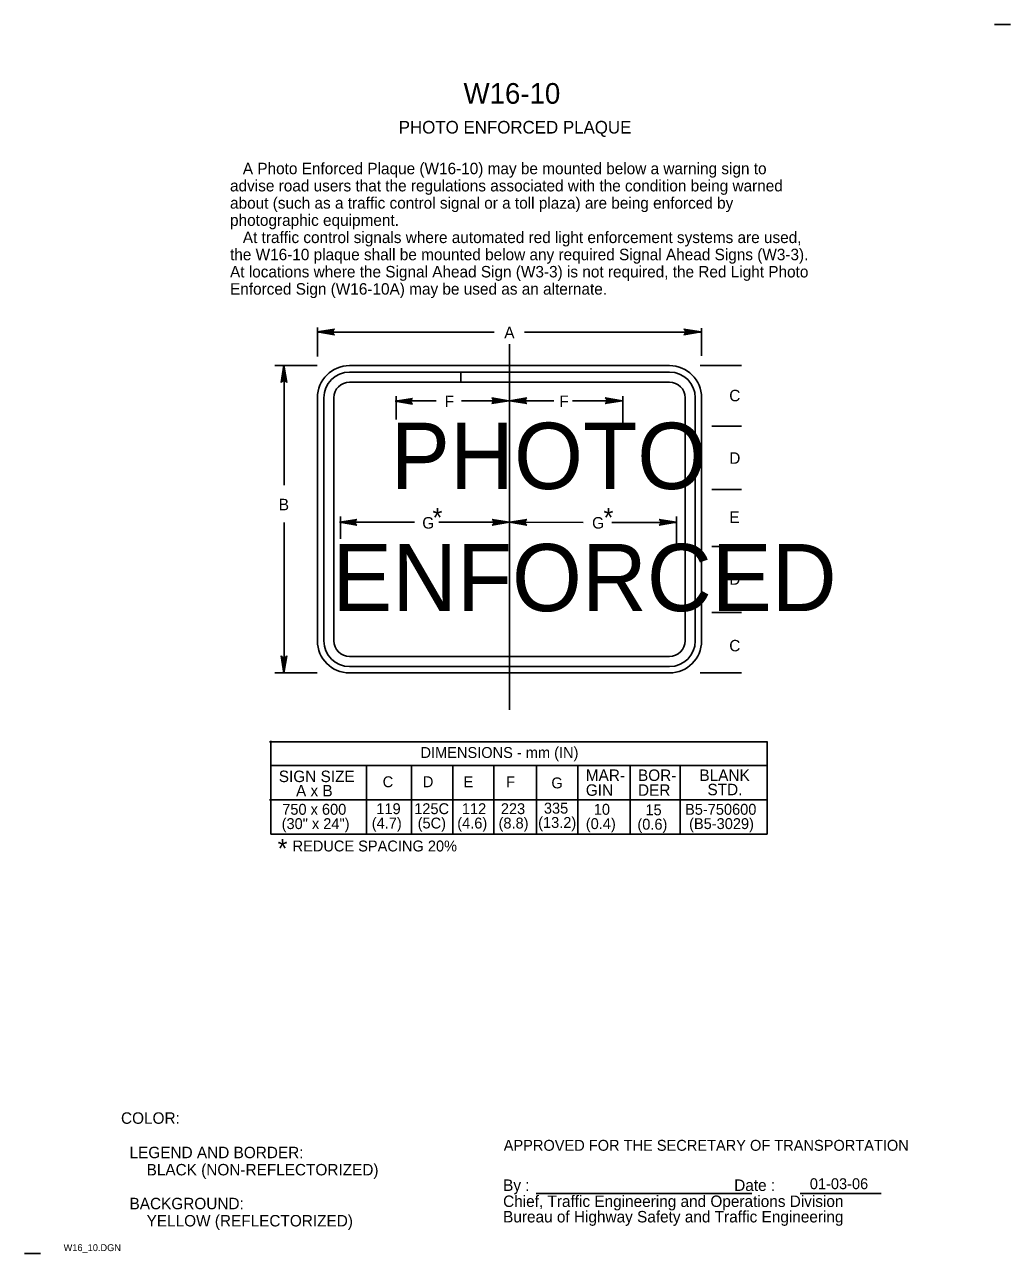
# Model space of a CAD drawing. Extents: x 0.004 to 0.219, y 0.004 to 0.272.
import ezdxf

# ---------------------------------------------------------------- set-up
doc = ezdxf.new("R2010")
doc.units = 0
for name, color, linetype in [('1', 7, 'Continuous'), ('2', 7, 'Continuous'), ('3', 7, 'Continuous'), ('4', 7, 'Continuous'), ('63', 7, 'Continuous')]:
    doc.layers.add(name, color=color, linetype=linetype)

# ---------------------------------------------------------------- blocks, each defined once
blk = doc.blocks.new('RARROW')
at = {"layer": '3'}
for p, q in [((-2.156, 0.285), (-2.2665, 0.384625)), ((-2.2665, 0.384625), (0, 0)), ((0, 0), (-2.2665, -0.379125)), ((-2.156, 0.285), (-2.075625, 0.12075)), ((0, 0), (-2.156, 0.285)), ((-2.14975, -0.2705), (0, 0)), ((-2.075625, 0.12075), (0, 0)), ((0, 0), (-2.074, -0.108)), ((-2.2665, -0.379125), (-2.14975, -0.2705)), ((-2.074, -0.108), (-2.14975, -0.2705))]:
    blk.add_line(p, q, dxfattribs=at)

msp = doc.modelspace()

# ---------------------------------------------------------------- linework, layer by layer
at = {"layer": '1'}
for p, q in [((0.10976, 0.20209), (0.10976, 0.12238)), ((0.05865, 0.19741), (0.06789, 0.19741)), ((0.06067, 0.17136), (0.06067, 0.19741)), ((0.14461, 0.19741), (0.07491, 0.19741)), ((0.09918, 0.19601), (0.07491, 0.19601)), ((0.09918, 0.19381), (0.09918, 0.19601)), ((0.09918, 0.19381), (0.09918, 0.19601)), ((0.14461, 0.19601), (0.09918, 0.19601)), ((0.09918, 0.19601), (0.09918, 0.19381)), ((0.07491, 0.19381), (0.09918, 0.19381)), ((0.09918, 0.19381), (0.14461, 0.19381)), ((0.06791, 0.13741), (0.06791, 0.19041)), ((0.06931, 0.19041), (0.06931, 0.13741)), ((0.07151, 0.13741), (0.07151, 0.19041)), ((0.08506, 0.19077), (0.08506, 0.18569)), ((0.13446, 0.19077), (0.13446, 0.18436)), ((0.14801, 0.19041), (0.14801, 0.13741)), ((0.15021, 0.13741), (0.15021, 0.19041)), ((0.15161, 0.13741), (0.15161, 0.19041)), ((0.16032, 0.18419), (0.15382, 0.18419)), ((0.15161, 0.13741), (0.15161, 0.17341)), ((0.16032, 0.17039), (0.15382, 0.17039)), ((0.07291, 0.15967), (0.07291, 0.16451)), ((0.14615, 0.15816), (0.14615, 0.16451)), ((0.06067, 0.13041), (0.06067, 0.16318)), ((0.16032, 0.15799), (0.15382, 0.15799)), ((0.16032, 0.14362), (0.15382, 0.14362)), ((0.14461, 0.13401), (0.07491, 0.13401)), ((0.07491, 0.13181), (0.14461, 0.13181)), ((0.05865, 0.13041), (0.06789, 0.13041)), ((0.14461, 0.13041), (0.07491, 0.13041)), ((0.16032, 0.13041), (0.15126, 0.13041)), ((0.11556, 0.01695), (0.16257, 0.01695)), ((0.17308, 0.01695), (0.19069, 0.01695))]:
    msp.add_line(p, q, dxfattribs=at)
for centre, radius, start, end in [((0.07491, 0.19041), 0.007, 90, 180), ((0.07491, 0.19041), 0.0056, 90, 180), ((0.14461, 0.19041), 0.007, 0, 90), ((0.14461, 0.19041), 0.0056, 0, 90), ((0.07491, 0.19041), 0.0034, 90, 180), ((0.14461, 0.19041), 0.0034, 0, 90), ((0.07491, 0.13741), 0.007, 180, 270), ((0.07491, 0.13741), 0.0056, 180, 270), ((0.07491, 0.13741), 0.0034, 180, 270), ((0.14461, 0.13741), 0.007, 270, 0), ((0.14461, 0.13741), 0.0056, 270, 0), ((0.14461, 0.13741), 0.0034, 270, 0)]:
    msp.add_arc(centre, radius, start, end, dxfattribs=at)
at = {"layer": '3'}
for p, q in [((0.06791, 0.19943), (0.06791, 0.20571)), ((0.10643, 0.2047), (0.06791, 0.2047)), ((0.1516, 0.2047), (0.11299, 0.2047)), ((0.1516, 0.19954), (0.1516, 0.20556)), ((0.15126, 0.19741), (0.16031, 0.19742)), ((0.09377, 0.18974), (0.08506, 0.18974)), ((0.10976, 0.18974), (0.09929, 0.18974)), ((0.11943, 0.18974), (0.10976, 0.18974)), ((0.13446, 0.18974), (0.12346, 0.18974)), ((0.08906, 0.16328), (0.07291, 0.1633)), ((0.10976, 0.16326), (0.09438, 0.16327)), ((0.12584, 0.16324), (0.10976, 0.16326)), ((0.14615, 0.16322), (0.13207, 0.16323)), ((0.0575, 0.11538), (0.16587, 0.11538)), ((0.05774, 0.11563), (0.05774, 0.09525)), ((0.16588, 0.11544), (0.16588, 0.09525)), ((0.16588, 0.11025), (0.05774, 0.11025)), ((0.07858, 0.11025), (0.07858, 0.09525)), ((0.13602, 0.11025), (0.13602, 0.09525)), ((0.14695, 0.11025), (0.14695, 0.09525)), ((0.0575, 0.10275), (0.16587, 0.10275)), ((0.16588, 0.09525), (0.05774, 0.09525))]:
    msp.add_line(p, q, dxfattribs=at)
for points in [[(0.08839, 0.11025), (0.08839, 0.09525)], [(0.09744, 0.11025), (0.09744, 0.09525)], [(0.10636, 0.11025), (0.10636, 0.09525)], [(0.11561, 0.11025), (0.11561, 0.09525)], [(0.12464, 0.11025), (0.12464, 0.09525)]]:
    msp.add_lwpolyline(points, dxfattribs=at)
at = {"layer": '63'}
for p, q in [((0.21888, 0.27175), (0.21538, 0.27175)), ((0.00762, 0.00387), (0.00413, 0.00387))]:
    msp.add_line(p, q, dxfattribs=at)

# ---------------------------------------------------------------- block references
at = {"layer": '3'}
for p, xscale, yscale, rotation in [((0.06788, 0.20475), 0.0016545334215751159, 0.0016366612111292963, 179.91708286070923), ((0.1515, 0.20475), 0.0016545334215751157, 0.001636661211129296, -0.08291713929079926), ((0.06062, 0.1975), 0.0016545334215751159, 0.0016366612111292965, 90.08291713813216), ((0.08488, 0.18963), 0.0016545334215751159, 0.0016366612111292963, 179.91708286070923), ((0.10963, 0.18975), 0.0016545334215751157, 0.001636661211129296, -0.08291713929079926), ((0.10975, 0.18975), 0.0016545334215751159, 0.0016366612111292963, 179.91708286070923), ((0.13437, 0.18975), 0.0016545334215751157, 0.001636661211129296, -0.08291713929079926), ((0.07275, 0.16325), 0.001654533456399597, 0.0016530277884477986, 179.91625369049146), ((0.10975, 0.16325), 0.0016545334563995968, 0.0016530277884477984, -0.08374630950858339), ((0.10975, 0.16325), 0.001654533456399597, 0.0016530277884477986, 179.91625369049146), ((0.14613, 0.16325), 0.0016545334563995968, 0.0016530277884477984, -0.08374630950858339), ((0.06062, 0.13037), 0.0016545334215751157, 0.0016366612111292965, -89.91708286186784)]:
    msp.add_blockref('RARROW', p, dxfattribs=dict(at, xscale=xscale, yscale=yscale, rotation=rotation))

# ---------------------------------------------------------------- texts
at = {"layer": '1'}
for s, height, p in [('W16-10', 0.0045, (0.09975, 0.2545)), ('PHOTO ENFORCED PLAQUE', 0.0027503, (0.08563, 0.248)), ('PHOTO', 0.014459, (0.08388, 0.1705)), ('*', 0.0041, (0.093, 0.16225)), ('*', 0.0041, (0.13025, 0.16225)), ('ENFORCED', 0.014645, (0.07113, 0.14388)), ('*', 0.0041, (0.05925, 0.09012)), ('COLOR:', 0.0025, (0.02513, 0.03213)), ('  LEGEND AND BORDER:', 0.0024998, (0.02513, 0.02463)), ('APPROVED FOR THE SECRETARY OF TRANSPORTATION', 0.0023752, (0.1085, 0.02625)), ('      BLACK (NON-REFLECTORIZED)', 0.0024998, (0.02513, 0.02088)), ('By :                                                Date :', 0.0024998, (0.10837, 0.0175)), ('Chief, Traffic Engineering and Operations Division', 0.0024998, (0.10837, 0.014)), ('  BACKGROUND:', 0.0024998, (0.02513, 0.0135)), ('      YELLOW (REFLECTORIZED)', 0.0024998, (0.02513, 0.00975)), ('Bureau of Highway Safety and Traffic Engineering', 0.0024998, (0.10837, 0.01063)), ('W16_10.DGN', 0.0015, (0.01263, 0.00438))]:
    msp.add_text(s, height=height, dxfattribs=at).set_placement(p)
at = {"layer": '2'}
for s, p in [('   A Photo Enforced Plaque (W16-10) may be mounted below a warning sign to', (0.04888, 0.23913)), ('advise road users that the regulations associated with the condition being warned', (0.04888, 0.23538)), ('about (such as a traffic control signal or a toll plaza) are being enforced by ', (0.04888, 0.23162)), ('photographic equipment.', (0.04888, 0.22787)), ('   At traffic control signals where automated red light enforcement systems are used,', (0.04888, 0.22412)), ('the W16-10 plaque shall be mounted below any required Signal Ahead Signs (W3-3).', (0.04888, 0.22038)), ('At locations where the Signal Ahead Sign (W3-3) is not required, the Red Light Photo', (0.04888, 0.21663)), ('Enforced Sign (W16-10A) may be used as an alternate.', (0.04888, 0.21288))]:
    msp.add_text(s, height=0.0024998, dxfattribs=at).set_placement(p)
at = {"layer": '3'}
for s, height, rotation, p in [('A', 0.0025, 359.9171, (0.10862, 0.20338)), ('F', 0.0025, 359.9171, (0.09563, 0.18838)), ('F', 0.0025, 0.0829, (0.12062, 0.18838)), ('C', 0.0025, 0.0829, (0.15763, 0.18963)), ('D', 0.0025, 0.0829, (0.15763, 0.176)), ('B', 0.0025, 0.0829, (0.0595, 0.16587)), ('G', 0.00252, 359.9163, (0.09075, 0.16187)), ('G', 0.00252, 0.0837, (0.12775, 0.16187)), ('E', 0.0025, 359.9171, (0.15763, 0.16312)), ('D', 0.0025, 359.9171, (0.15763, 0.14963)), ('C', 0.0025, 359.9171, (0.15763, 0.13512))]:
    msp.add_text(s, height=height, rotation=rotation, dxfattribs=at).set_placement(p)
for s, height, p in [('DIMENSIONS - mm (IN)', 0.0023752, (0.09037, 0.11188)), ('SIGN SIZE', 0.0025, (0.0595, 0.10662)), ('C', 0.00238, (0.08213, 0.1055)), ('D', 0.00238, (0.09087, 0.1055)), ('E', 0.00238, (0.09975, 0.1055)), ('F', 0.00238, (0.109, 0.1055)), ('G', 0.00238, (0.11888, 0.10525)), ('MAR-', 0.0025, (0.12638, 0.10687)), ('BOR-', 0.0025, (0.13775, 0.10687)), ('BLANK', 0.0025, (0.15113, 0.10687)), ('A x B', 0.0025, (0.06325, 0.1035)), ('GIN', 0.0025, (0.12638, 0.10363)), ('DER', 0.0025, (0.13775, 0.10363)), ('STD.', 0.0025, (0.15288, 0.10375)), ('750 x 600', 0.002375, (0.06025, 0.0995)), ('119', 0.002375, (0.08075, 0.09963)), ('125C', 0.002375, (0.089, 0.09963)), ('112', 0.002375, (0.09938, 0.09963)), ('223', 0.002375, (0.10787, 0.09963)), ('335', 0.002375, (0.11725, 0.09975)), ('10', 0.002375, (0.12812, 0.0995)), ('B5-750600', 0.002375, (0.148, 0.0995)), ('(13.2)', 0.002375, (0.116, 0.09663)), ('15', 0.002375, (0.13937, 0.09938)), ('(30" x 24")', 0.0023752, (0.06012, 0.09638)), ('(4.7)', 0.002375, (0.07975, 0.0965)), ('(5C)', 0.002375, (0.08975, 0.0965)), ('(4.6)', 0.002375, (0.09838, 0.0965)), ('(8.8)', 0.002375, (0.10737, 0.0965)), ('(0.4)', 0.002375, (0.12638, 0.09638)), ('(0.6)', 0.002375, (0.13762, 0.09625)), ('(B5-3029)', 0.002375, (0.14888, 0.09638)), ('REDUCE SPACING 20%', 0.0023752, (0.0625, 0.0915))]:
    msp.add_text(s, height=height, dxfattribs=at).set_placement(p)
at = {"layer": '4'}
msp.add_text('01-03-06', height=0.002375, dxfattribs=at).set_placement((0.17518, 0.01788))

doc.saveas('drawing.dxf')
